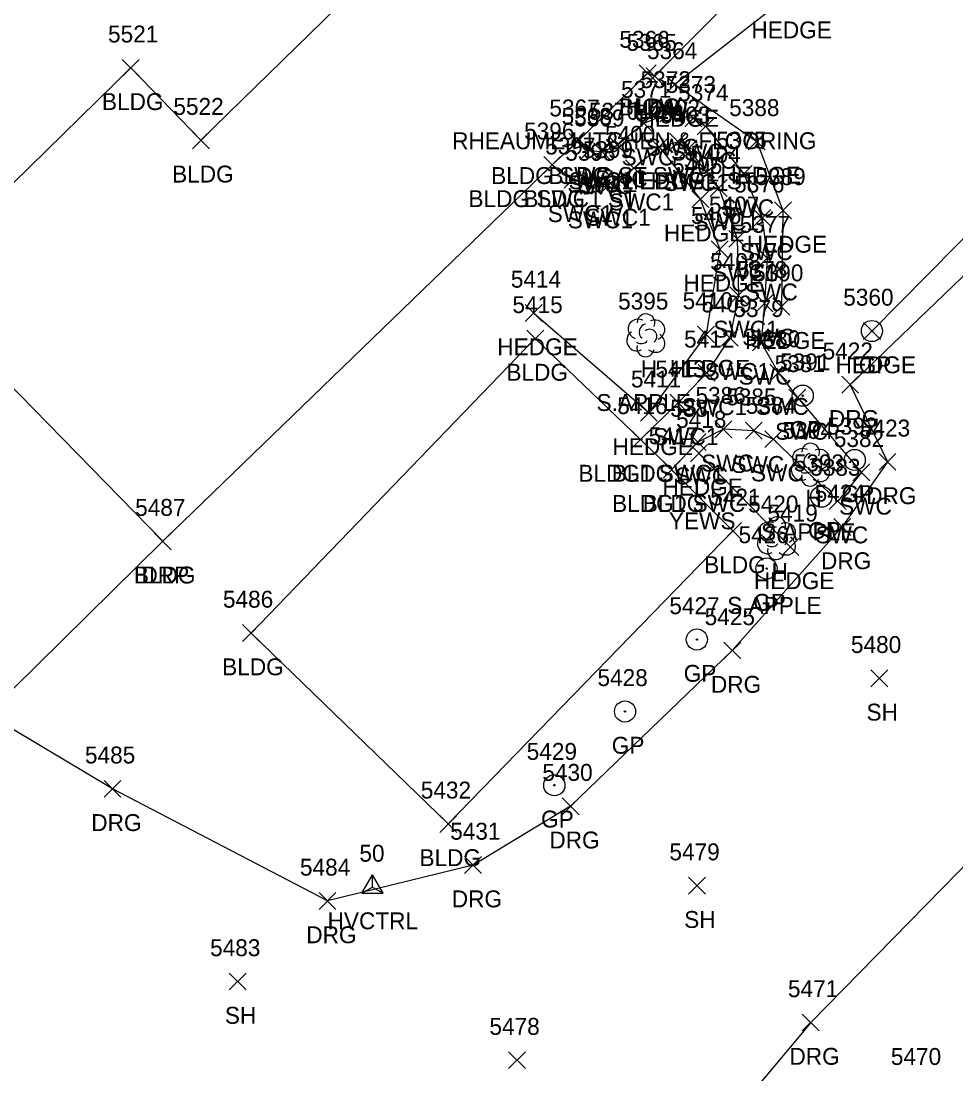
# Model space of a CAD drawing. Extents: x 1472233 to 1475777, y 540726 to 543442.
# Drawn here: x 1474616.2 to 1474726.8, y 541355.8 to 541480.4 of the extents above; entities that cross this region are included whole.
import ezdxf

# ---------------------------------------------------------------- set-up
doc = ezdxf.new("R2010")
doc.units = 0
for name, color, linetype in [('C_A', 7, 'Continuous'), ('C_I', 7, 'Continuous'), ('CPSM', 7, 'Continuous'), ('L_A', 7, 'Continuous'), ('L_C', 7, 'Continuous'), ('L_I', 7, 'Continuous'), ('L_TIC', 7, 'Continuous'), ('LAHR', 7, 'Continuous'), ('LBC', 7, 'Continuous'), ('LTD', 7, 'Continuous'), ('R_A', 7, 'Continuous'), ('R_I', 7, 'Continuous'), ('R_TIC', 7, 'Continuous'), ('RDG', 7, 'Continuous'), ('RDP', 7, 'Continuous'), ('RGP', 7, 'Continuous'), ('RSW', 7, 'Continuous')]:
    doc.layers.add(name, color=color, linetype=linetype)

msp = doc.modelspace()

# ---------------------------------------------------------------- linework, layer by layer
at = {"layer": 'CPSM'}
for p, q in [((1474656.5, 541377.23), (1474657.75, 541379.4)), ((1474659, 541377.23), (1474657.75, 541379.4)), ((1474657.75, 541377.95), (1474657.75, 541379.4)), ((1474656.5, 541377.23), (1474657.75, 541377.95)), ((1474657.75, 541377.95), (1474657.75, 541377.95)), ((1474657.75, 541377.95), (1474659, 541377.23)), ((1474656.5, 541377.23), (1474659, 541377.23))]:
    msp.add_line(p, q, dxfattribs=at)
at = {"layer": 'L_TIC'}
for points in [[(1474628.16, 541473.87), (1474630.16, 541475.87)], [(1474630.16, 541473.87), (1474628.16, 541475.87)], [(1474689.31, 541473.24), (1474691.31, 541475.24)], [(1474691.31, 541473.24), (1474689.31, 541475.24)], [(1474689.31, 541473.24), (1474691.31, 541475.24)], [(1474691.31, 541473.24), (1474689.31, 541475.24)], [(1474690.12, 541472.88), (1474692.12, 541474.88)], [(1474692.12, 541472.88), (1474690.12, 541474.88)], [(1474692.53, 541471.9), (1474694.53, 541473.9)], [(1474694.53, 541471.9), (1474692.53, 541473.9)], [(1474636.46, 541465.3), (1474638.46, 541467.3)], [(1474638.46, 541465.3), (1474636.46, 541467.3)], [(1474680.97, 541465.12), (1474682.97, 541467.12)], [(1474682.97, 541465.12), (1474680.97, 541467.12)], [(1474690.64, 541464.51), (1474692.64, 541466.51)], [(1474692.64, 541464.51), (1474690.64, 541466.51)], [(1474702.2, 541465.16), (1474704.2, 541467.16)], [(1474704.2, 541465.16), (1474702.2, 541467.16)], [(1474678, 541462.39), (1474680, 541464.39)], [(1474680, 541462.39), (1474678, 541464.39)], [(1474695.52, 541458.33), (1474697.52, 541460.33)], [(1474697.52, 541458.33), (1474695.52, 541460.33)], [(1474705.3, 541457), (1474707.3, 541459)], [(1474707.3, 541457), (1474705.3, 541459)], [(1474697.82, 541452.4), (1474699.82, 541454.4)], [(1474699.82, 541452.4), (1474697.82, 541454.4)], [(1474705.12, 541445.61), (1474707.12, 541447.61)], [(1474707.12, 541445.61), (1474705.12, 541447.61)], [(1474675.8, 541444.86), (1474677.8, 541446.86)], [(1474677.8, 541444.86), (1474675.8, 541446.86)], [(1474676, 541441.85), (1474678, 541443.85)], [(1474678, 541441.85), (1474676, 541443.85)], [(1474676, 541441.85), (1474678, 541443.85)], [(1474678, 541441.85), (1474676, 541443.85)], [(1474696.21, 541442.32), (1474698.21, 541444.32)], [(1474698.21, 541442.32), (1474696.21, 541444.32)], [(1474715.82, 541442.73), (1474717.82, 541444.73)], [(1474717.82, 541442.73), (1474715.82, 541444.73)], [(1474689.44, 541433.05), (1474691.44, 541435.05)], [(1474691.44, 541433.05), (1474689.44, 541435.05)], [(1474688.45, 541429.9), (1474690.45, 541431.9)], [(1474690.45, 541429.9), (1474688.45, 541431.9)], [(1474695.35, 541428.27), (1474697.35, 541430.27)], [(1474697.35, 541428.27), (1474695.35, 541430.27)], [(1474692.12, 541426.33), (1474694.12, 541428.33)], [(1474694.12, 541426.33), (1474692.12, 541428.33)], [(1474699.39, 541419.08), (1474701.39, 541421.08)], [(1474701.39, 541419.08), (1474699.39, 541421.08)], [(1474631.94, 541417.86), (1474633.94, 541419.86)], [(1474633.94, 541417.86), (1474631.94, 541419.86)], [(1474706.17, 541417.19), (1474708.17, 541419.19)], [(1474708.17, 541417.19), (1474706.17, 541419.19)], [(1474642.38, 541407), (1474644.38, 541409)], [(1474644.38, 541407), (1474642.38, 541409)], [(1474642.38, 541407), (1474644.38, 541409)], [(1474644.38, 541407), (1474642.38, 541409)], [(1474716.69, 541401.64), (1474718.69, 541403.64)], [(1474718.69, 541401.64), (1474716.69, 541403.64)], [(1474665.72, 541384.42), (1474667.72, 541386.42)], [(1474667.72, 541384.42), (1474665.72, 541386.42)], [(1474695.14, 541377.11), (1474697.14, 541379.11)], [(1474697.14, 541377.11), (1474695.14, 541379.11)], [(1474640.8, 541365.77), (1474642.8, 541367.77)], [(1474642.8, 541365.77), (1474640.8, 541367.77)], [(1474673.84, 541356.46), (1474675.84, 541358.46)], [(1474675.84, 541356.46), (1474673.84, 541358.46)]]:
    msp.add_lwpolyline(points, dxfattribs=at)
at = {"layer": 'LAHR'}
for points in [[(1474723.23, 541499.5), (1474706.87, 541483.35), (1474693.53, 541472.9), (1474703.2, 541466.16), (1474706.3, 541458), (1474706.12, 541446.61)], [(1474755.53, 541485.45), (1474742.31, 541469.68), (1474733.53, 541460.65), (1474716.82, 541443.73)], [(1474691.64, 541465.51), (1474696.52, 541459.33), (1474698.82, 541453.4), (1474697.21, 541443.32), (1474690.44, 541434.05), (1474676.8, 541445.86)], [(1474696.35, 541429.27), (1474707.17, 541418.19)]]:
    msp.add_lwpolyline(points, dxfattribs=at)
at = {"layer": 'LBC'}
for points in [[(1474667.61, 541497.68), (1474686.46, 541515.6), (1474709.41, 541493.59), (1474710.11, 541492.87), (1474691.12, 541473.88), (1474690.31, 541474.24)], [(1474690.31, 541474.24), (1474681.97, 541466.12), (1474679, 541463.39), (1474632.94, 541418.86), (1474609.18, 541443.15), (1474603.1, 541449.36), (1474629.16, 541474.87), (1474637.46, 541466.3), (1474668, 541496.15)], [(1474677, 541442.85), (1474689.45, 541430.9), (1474693.12, 541427.33), (1474700.39, 541420.08), (1474666.72, 541385.42), (1474643.38, 541408)], [(1474677, 541442.85), (1474643.38, 541408)]]:
    msp.add_lwpolyline(points, dxfattribs=at)
at = {"layer": 'LTD'}
for p, q in [((1474690.06, 541443.27), (1474690.06, 541443.27)), ((1474690.06, 541443.27), (1474690.06, 541443.27)), ((1474709.52, 541427.96), (1474709.52, 541427.96)), ((1474709.52, 541427.96), (1474709.52, 541427.96)), ((1474705.52, 541419.27), (1474705.52, 541419.27)), ((1474705.52, 541419.27), (1474705.52, 541419.27))]:
    msp.add_line(p, q, dxfattribs=at)
for centre in [(1474690.1, 541444.7), (1474709.57, 541429.4), (1474705.57, 541420.7)]:
    msp.add_arc(centre, 1.05, 335.5272, 180.9563, dxfattribs=at)
for centre, major_axis, ratio, start_param, end_param in [((1474689.27, 541443.93), (1.21, -0.51), 0.895232, 1.570796, 4.712389), ((1474691.1, 541443.85), (-1.14, -0.48), 0.949671, 1.570796, 4.712389), ((1474688.97, 541442.56), (0.58, -1.04), 0.959034, 3.141593, 6.283185), ((1474689.85, 541443.73), (-0.208, -0.792), 0.645439, 3.141593, 6.283185), ((1474690.56, 541443.1), (-0.5, 0.667), 0.989748, 3.141593, 6.283185), ((1474689.6, 541442.52), (-0.625, -0.083), 0.423636, 0, 3.141593), ((1474691.06, 541442.43), (-1.09, 0.79), 0.841452, 1.570796, 4.712389), ((1474690.06, 541441.77), (0.26, 1.06), 0.942809, 1.570796, 4.712389), ((1474708.73, 541428.63), (1.21, -0.51), 0.895232, 1.570796, 4.712389), ((1474710.57, 541428.55), (-1.14, -0.48), 0.949671, 1.570796, 4.712389), ((1474709.32, 541428.42), (-0.208, -0.792), 0.645439, 3.141593, 6.283185), ((1474710.02, 541427.8), (-0.5, 0.667), 0.989748, 3.141593, 6.283185), ((1474708.44, 541427.26), (0.58, -1.04), 0.959034, 3.141593, 6.283185), ((1474710.52, 541427.13), (-1.09, 0.79), 0.841452, 1.570796, 4.712389), ((1474709.52, 541426.46), (0.26, 1.06), 0.942809, 1.570796, 4.712389), ((1474709.07, 541427.21), (-0.625, -0.083), 0.423636, 0, 3.141593), ((1474704.73, 541419.94), (1.21, -0.51), 0.895232, 1.570796, 4.712389), ((1474706.56, 541419.85), (-1.14, -0.48), 0.949671, 1.570796, 4.712389), ((1474705.31, 541419.73), (-0.208, -0.792), 0.645439, 3.141593, 6.283185), ((1474706.02, 541419.1), (-0.5, 0.667), 0.989748, 3.141593, 6.283185), ((1474704.44, 541418.56), (0.58, -1.04), 0.959034, 3.141593, 6.283185), ((1474706.52, 541418.44), (-1.09, 0.79), 0.841452, 1.570796, 4.712389), ((1474705.52, 541417.77), (0.26, 1.06), 0.942809, 1.570796, 4.712389), ((1474705.06, 541418.52), (-0.625, -0.083), 0.423636, 0, 3.141593)]:
    msp.add_ellipse(centre, major_axis=major_axis, ratio=ratio, start_param=start_param, end_param=end_param, dxfattribs=at)
at = {"layer": 'R_TIC'}
for points in [[(1474691.72, 541468.47), (1474693.72, 541470.47)], [(1474693.72, 541468.47), (1474691.72, 541470.47)], [(1474694.69, 541467.9), (1474696.69, 541469.9)], [(1474696.69, 541467.9), (1474694.69, 541469.9)], [(1474688.84, 541467.32), (1474690.84, 541469.32)], [(1474690.84, 541467.32), (1474688.84, 541469.32)], [(1474696.17, 541466.93), (1474698.17, 541468.93)], [(1474698.17, 541466.93), (1474696.17, 541468.93)], [(1474680.97, 541465.12), (1474682.97, 541467.12)], [(1474682.97, 541465.12), (1474680.97, 541467.12)], [(1474682.43, 541464.13), (1474684.43, 541466.13)], [(1474684.43, 541464.13), (1474682.43, 541466.13)], [(1474685.69, 541464.73), (1474687.69, 541466.73)], [(1474687.69, 541464.73), (1474685.69, 541466.73)], [(1474690.64, 541464.51), (1474692.64, 541466.51)], [(1474692.64, 541464.51), (1474690.64, 541466.51)], [(1474692.87, 541465.12), (1474694.87, 541467.12)], [(1474694.87, 541465.12), (1474692.87, 541467.12)], [(1474694.1, 541464.3), (1474696.1, 541466.3)], [(1474696.1, 541464.3), (1474694.1, 541466.3)], [(1474683.92, 541463.94), (1474685.92, 541465.94)], [(1474685.92, 541463.94), (1474683.92, 541465.94)], [(1474678, 541462.39), (1474680, 541464.39)], [(1474680, 541462.39), (1474678, 541464.39)], [(1474687.68, 541462), (1474689.68, 541464)], [(1474689.68, 541462), (1474687.68, 541464)], [(1474680.44, 541460.62), (1474682.44, 541462.62)], [(1474682.44, 541460.62), (1474680.44, 541462.62)], [(1474700.67, 541461.31), (1474702.67, 541463.31)], [(1474702.67, 541461.31), (1474700.67, 541463.31)], [(1474682.81, 541459.88), (1474684.81, 541461.88)], [(1474684.81, 541459.88), (1474682.81, 541461.88)], [(1474684.89, 541460.19), (1474686.89, 541462.19)], [(1474686.89, 541460.19), (1474684.89, 541462.19)], [(1474697.7, 541459.64), (1474699.7, 541461.64)], [(1474699.7, 541459.64), (1474697.7, 541461.64)], [(1474702.85, 541456.12), (1474704.85, 541458.12)], [(1474704.85, 541456.12), (1474702.85, 541458.12)], [(1474699.88, 541453.64), (1474701.88, 541455.64)], [(1474701.88, 541453.64), (1474699.88, 541455.64)], [(1474703.44, 541451.35), (1474705.44, 541453.35)], [(1474705.44, 541451.35), (1474703.44, 541453.35)], [(1474700.03, 541446.95), (1474702.03, 541448.95)], [(1474702.03, 541446.95), (1474700.03, 541448.95)], [(1474703.12, 541446), (1474705.12, 541448)], [(1474705.12, 541446), (1474703.12, 541448)], [(1474699, 541441.94), (1474701, 541443.94)], [(1474701, 541441.94), (1474699, 541443.94)], [(1474702.71, 541441.39), (1474704.71, 541443.39)], [(1474704.71, 541441.39), (1474702.71, 541443.39)], [(1474696.29, 541437.78), (1474698.29, 541439.78)], [(1474698.29, 541437.78), (1474696.29, 541439.78)], [(1474704.74, 541437.81), (1474706.74, 541439.81)], [(1474706.74, 541437.81), (1474704.74, 541439.81)], [(1474713.25, 541436.37), (1474715.25, 541438.37)], [(1474715.25, 541436.37), (1474713.25, 541438.37)], [(1474692.9, 541434.24), (1474694.9, 541436.24)], [(1474694.9, 541434.24), (1474692.9, 541436.24)], [(1474707.01, 541434.87), (1474709.01, 541436.87)], [(1474709.01, 541434.87), (1474707.01, 541436.87)], [(1474698.26, 541431.11), (1474700.26, 541433.11)], [(1474700.26, 541431.11), (1474698.26, 541433.11)], [(1474701.85, 541430.94), (1474703.85, 541432.94)], [(1474703.85, 541430.94), (1474701.85, 541432.94)], [(1474688.45, 541429.9), (1474690.45, 541431.9)], [(1474690.45, 541429.9), (1474688.45, 541431.9)], [(1474695.22, 541429.59), (1474697.22, 541431.59)], [(1474697.22, 541429.59), (1474695.22, 541431.59)], [(1474704.16, 541429.94), (1474706.16, 541431.94)], [(1474706.16, 541429.94), (1474704.16, 541431.94)], [(1474717.66, 541427.25), (1474719.66, 541429.25)], [(1474719.66, 541427.25), (1474717.66, 541429.25)], [(1474692.12, 541426.33), (1474694.12, 541428.33)], [(1474694.12, 541426.33), (1474692.12, 541428.33)], [(1474714.58, 541426.01), (1474716.58, 541428.01)], [(1474716.58, 541426.01), (1474714.58, 541428.01)], [(1474711.78, 541422.61), (1474713.78, 541424.61)], [(1474713.78, 541422.61), (1474711.78, 541424.61)], [(1474712.31, 541419.55), (1474714.31, 541421.55)], [(1474714.31, 541419.55), (1474712.31, 541421.55)], [(1474631.94, 541417.86), (1474633.94, 541419.86)], [(1474633.94, 541417.86), (1474631.94, 541419.86)], [(1474699.3, 541404.93), (1474701.3, 541406.93)], [(1474701.3, 541404.93), (1474699.3, 541406.93)], [(1474626, 541388.57), (1474628, 541390.57)], [(1474628, 541388.57), (1474626, 541390.57)], [(1474680.18, 541386.51), (1474682.18, 541388.51)], [(1474682.18, 541386.51), (1474680.18, 541388.51)], [(1474668.64, 541379.55), (1474670.64, 541381.55)], [(1474670.64, 541379.55), (1474668.64, 541381.55)], [(1474651.43, 541375.3), (1474653.43, 541377.3)], [(1474653.43, 541375.3), (1474651.43, 541377.3)], [(1474708.58, 541360.92), (1474710.58, 541362.92)], [(1474710.58, 541360.92), (1474708.58, 541362.92)]]:
    msp.add_lwpolyline(points, dxfattribs=at)
at = {"layer": 'RDG'}
for points in [[(1474750.77, 541472.47), (1474714.25, 541437.37), (1474718.66, 541428.25), (1474713.31, 541420.55), (1474700.3, 541405.93), (1474681.18, 541387.51), (1474669.64, 541380.55), (1474652.43, 541376.3), (1474627, 541389.57), (1474612.18, 541398.39)], [(1474771.15, 541451.97), (1474774.94, 541432.6), (1474736.77, 541389.66), (1474709.58, 541361.92), (1474688.69, 541336.96), (1474660.55, 541324.88), (1474605.14, 541322.61), (1474559.08, 541319.27), (1474530.64, 541317.68), (1474505.35, 541356.73), (1474510.5, 541370.9), (1474529.64, 541392.89), (1474545.34, 541414.19), (1474568.38, 541444.04), (1474582.3, 541429.97)]]:
    msp.add_lwpolyline(points, dxfattribs=at)
at = {"layer": 'RDP'}
msp.add_lwpolyline([(1474632.94, 541418.86), (1474612.18, 541398.39), (1474590.26, 541420.46), (1474607.11, 541436.66), (1474606.73, 541439.08), (1474607.53, 541441.26), (1474609.18, 541443.15)], dxfattribs=at)
at = {"layer": 'RGP'}
for p, q in [((1474716.82, 541443.73), (1474716.82, 541443.73)), ((1474708.64, 541436.08), (1474708.64, 541436.08)), ((1474714.79, 541428.48), (1474714.79, 541428.48)), ((1474710.84, 541424.13), (1474710.84, 541424.13)), ((1474704.36, 541415.63), (1474704.36, 541415.63)), ((1474696.12, 541407.23), (1474696.12, 541407.23)), ((1474687.62, 541398.72), (1474687.62, 541398.72)), ((1474679.26, 541389.99), (1474679.26, 541389.99))]:
    msp.add_line(p, q, dxfattribs=at)
for centre, radius in [((1474716.82, 541443.73), 1.25), ((1474716.82, 541443.73), 0.0833), ((1474708.64, 541436.08), 1.25), ((1474708.64, 541436.08), 0.0833), ((1474714.79, 541428.48), 1.25), ((1474714.79, 541428.48), 0.0833), ((1474710.84, 541424.13), 1.25), ((1474710.84, 541424.13), 0.0833), ((1474704.36, 541415.63), 1.25), ((1474704.36, 541415.63), 0.0833), ((1474696.12, 541407.23), 1.25), ((1474696.12, 541407.23), 0.0833), ((1474687.62, 541398.72), 1.25), ((1474687.62, 541398.72), 0.0833), ((1474679.26, 541389.99), 1.25), ((1474679.26, 541389.99), 0.0833)]:
    msp.add_circle(centre, radius, dxfattribs=at)
at = {"layer": 'RSW'}
for points in [[(1474681.97, 541466.12), (1474683.43, 541465.13), (1474684.92, 541464.94), (1474686.69, 541465.73), (1474689.84, 541468.32), (1474692.72, 541469.47), (1474695.69, 541468.9), (1474697.17, 541467.93), (1474701.67, 541462.31), (1474703.85, 541457.12), (1474704.44, 541452.35), (1474704.12, 541447), (1474703.71, 541442.39), (1474705.74, 541438.81), (1474708.01, 541435.87), (1474715.58, 541427.01), (1474712.78, 541423.61), (1474705.16, 541430.94), (1474702.85, 541431.94), (1474699.26, 541432.11), (1474696.22, 541430.59), (1474693.12, 541427.33)], [(1474679, 541463.39), (1474681.44, 541461.62), (1474683.81, 541460.88), (1474685.89, 541461.19), (1474688.68, 541463), (1474691.64, 541465.51), (1474693.87, 541466.12), (1474695.1, 541465.3), (1474698.7, 541460.64), (1474700.88, 541454.64), (1474701.03, 541447.95), (1474700, 541442.94), (1474697.29, 541438.78), (1474693.9, 541435.24), (1474689.45, 541430.9)]]:
    msp.add_lwpolyline(points, dxfattribs=at)

# ---------------------------------------------------------------- texts
at = {"layer": 'C_A'}
msp.add_text('HVCTRL', height=2, dxfattribs=at).set_placement((1474652.44, 541372.95))
at = {"layer": 'C_I'}
msp.add_text('50', height=2, dxfattribs=at).set_placement((1474656.2, 541380.95))
at = {"layer": 'L_A'}
for s, p in [('HEDGE', (1474702.57, 541478.35)), ('BLDG', (1474625.75, 541469.87)), ('BLDG', (1474686.9, 541469.24)), ('HOW', (1474687.7, 541469.24)), ('HOW', (1474688.5, 541468.88)), ('HEDGE', (1474689.23, 541467.9)), ('BLDG', (1474634.05, 541461.3)), ('BLDG', (1474678.56, 541461.12)), ('HEDGE', (1474687.34, 541460.51)), ('HEDGE', (1474698.9, 541461.16)), ('BLDG', (1474675.59, 541458.39)), ('HEDGE', (1474692.22, 541454.33)), ('HEDGE', (1474702.01, 541453)), ('HEDGE', (1474694.52, 541448.4)), ('HEDGE', (1474701.82, 541441.61)), ('HEDGE', (1474672.51, 541440.86)), ('BLDG', (1474673.59, 541437.85)), ('BLDG', (1474673.59, 541437.85)), ('H', (1474689.49, 541438.27)), ('HEDGE', (1474692.91, 541438.32)), ('HEDGE', (1474712.52, 541438.73)), ('HEDGE', (1474686.14, 541429.05)), ('BLDG', (1474686.04, 541425.9)), ('HEDGE', (1474692.05, 541424.27)), ('H', (1474708.96, 541422.96)), ('BLDG', (1474689.71, 541422.33)), ('BLDG', (1474696.98, 541415.08)), ('H', (1474704.96, 541414.27)), ('BLDG', (1474629.53, 541413.86)), ('HEDGE', (1474702.87, 541413.19)), ('BLDG', (1474639.97, 541403)), ('BLDG', (1474639.97, 541403)), ('SH', (1474716.18, 541397.64)), ('BLDG', (1474663.31, 541380.42)), ('SH', (1474694.62, 541373.11)), ('SH', (1474640.29, 541361.77))]:
    msp.add_text(s, height=2, dxfattribs=at).set_placement(p)
at = {"layer": 'L_C'}
for s, p in [('RHEAUME KITCHEN & FLOORING', (1474667.17, 541465.24)), ('S.APPLE', (1474684.25, 541434.27)), ('YEWS', (1474692.81, 541420.27)), ('S.APPLE', (1474703.71, 541418.96)), ('S.APPLE', (1474699.71, 541410.27))]:
    msp.add_text(s, height=2, dxfattribs=at).set_placement(p)
at = {"layer": 'L_I'}
for s, p in [('5521', (1474626.47, 541477.87)), ('5366', (1474686.95, 541477.24)), ('5366', (1474686.95, 541477.24)), ('5365', (1474687.81, 541476.88)), ('5364', (1474690.22, 541475.9)), ('5522', (1474634.2, 541469.3)), ('5367', (1474678.67, 541469.12)), ('5388', (1474699.94, 541469.16)), ('5401', (1474688.87, 541468.51)), ('5396', (1474675.68, 541466.39)), ('5405', (1474693.18, 541462.33)), ('5389', (1474703.04, 541461)), ('5406', (1474695.43, 541456.4)), ('5390', (1474702.77, 541449.61)), ('5414', (1474674.11, 541448.86)), ('5360', (1474713.43, 541446.73)), ('5415', (1474674.3, 541445.85)), ('5415', (1474674.3, 541445.85)), ('5395', (1474686.8, 541446.27)), ('5410', (1474694.43, 541446.32)), ('5411', (1474688.32, 541437.05)), ('5416', (1474686.7, 541433.9)), ('5418', (1474693.66, 541432.27)), ('5394', (1474706.26, 541430.96)), ('5417', (1474690.42, 541430.33)), ('5421', (1474697.7, 541423.08)), ('5487', (1474629.68, 541421.86)), ('5420', (1474702.18, 541422.27)), ('5419', (1474704.47, 541421.19)), ('5486', (1474640.06, 541411)), ('5486', (1474640.06, 541411)), ('5480', (1474714.34, 541405.64)), ('5432', (1474663.46, 541388.42)), ('5479', (1474692.87, 541381.11)), ('5483', (1474638.54, 541369.77)), ('5478', (1474671.58, 541360.46)), ('5470', (1474719.06, 541356.9))]:
    msp.add_text(s, height=2, dxfattribs=at).set_placement(p)
at = {"layer": 'R_A'}
for s, p in [('SWC', (1474690.09, 541464.47)), ('SWC', (1474687.21, 541463.32)), ('SWC', (1474693.05, 541463.9)), ('SWC', (1474694.54, 541462.93)), ('BLDG SWC ST', (1474671.79, 541461.12)), ('SWC1 HEDGE ST', (1474680.94, 541460.51)), ('SWC', (1474684.05, 541460.73)), ('SWC1', (1474690.91, 541461.12)), ('SWC1', (1474692.14, 541460.3)), ('SWC', (1474680.79, 541460.13)), ('SWC', (1474682.28, 541459.94)), ('BLDG SWC1 ST', (1474669.1, 541458.39)), ('SWC1', (1474685.71, 541458)), ('SWC1', (1474678.48, 541456.62)), ('SWC', (1474699.03, 541457.31)), ('SWC1', (1474680.85, 541455.88)), ('SWC1', (1474682.93, 541456.19)), ('SWC1', (1474695.74, 541455.64)), ('SWC', (1474701.21, 541452.12)), ('SWC1', (1474697.92, 541449.64)), ('SWC', (1474701.81, 541447.35)), ('SWC1', (1474698.07, 541442.95)), ('SWC', (1474701.48, 541442)), ('SWC1', (1474697.04, 541437.94)), ('GP', (1474715.25, 541438.73)), ('SWC', (1474701.07, 541437.39)), ('SWC1', (1474694.33, 541433.78)), ('SWC', (1474703.1, 541433.81)), ('DRG', (1474711.74, 541432.37)), ('SWC', (1474705.37, 541430.87)), ('GP', (1474707.07, 541431.08)), ('SWC1', (1474690.94, 541430.24)), ('SWC', (1474696.62, 541427.11)), ('SWC', (1474700.21, 541426.94)), ('BLDG1 SWC1', (1474682.1, 541425.9)), ('SWC', (1474693.58, 541425.59)), ('SWC', (1474702.52, 541425.94)), ('GP', (1474713.22, 541423.48)), ('DRG', (1474716.15, 541423.25)), ('BLDG1 SWC', (1474686.09, 541422.33)), ('SWC', (1474712.94, 541422.01)), ('GP', (1474709.27, 541419.13)), ('SWC', (1474710.14, 541418.61)), ('DRG', (1474710.8, 541415.55)), ('DRP', (1474630.43, 541413.86)), ('GP', (1474702.79, 541410.63)), ('GP', (1474694.56, 541402.23)), ('DRG', (1474697.78, 541400.93)), ('GP', (1474686.05, 541393.72)), ('DRG', (1474624.49, 541384.57)), ('GP', (1474677.69, 541384.99)), ('DRG', (1474678.67, 541382.51)), ('DRG', (1474667.13, 541375.55)), ('DRG', (1474649.92, 541371.3)), ('DRG', (1474707.07, 541356.92))]:
    msp.add_text(s, height=2, dxfattribs=at).set_placement(p)
at = {"layer": 'R_I'}
for s, p in [('5372', (1474689.46, 541472.47)), ('5373', (1474692.43, 541471.9)), ('5371', (1474687.15, 541471.32)), ('5374', (1474693.91, 541470.93)), ('5367', (1474678.67, 541469.12)), ('5402', (1474690.53, 541469.12)), ('5368', (1474680.12, 541468.13)), ('5369', (1474681.61, 541467.94)), ('5370', (1474683.34, 541468.73)), ('5401', (1474688.87, 541468.51)), ('5403', (1474691.77, 541468.3)), ('5396', (1474675.68, 541466.39)), ('5400', (1474685.25, 541466)), ('5375', (1474698.41, 541465.31)), ('5397', (1474678.18, 541464.62)), ('5399', (1474682.62, 541464.19)), ('5398', (1474680.55, 541463.88)), ('5404', (1474695.36, 541463.64)), ('5376', (1474700.53, 541460.12)), ('5407', (1474697.55, 541457.64)), ('5377', (1474701.18, 541455.35)), ('5408', (1474697.69, 541450.95)), ('5378', (1474700.86, 541450)), ('5360', (1474713.43, 541446.73)), ('5409', (1474696.65, 541445.94)), ('5379', (1474700.44, 541445.39)), ('5412', (1474694.6, 541441.78)), ('5380', (1474702.39, 541441.81)), ('5422', (1474710.99, 541440.37)), ('5391', (1474705.95, 541439.08)), ('5413', (1474691.21, 541438.24)), ('5381', (1474705.32, 541438.87)), ('5386', (1474695.95, 541435.11)), ('5385', (1474699.59, 541434.94)), ('5416', (1474686.7, 541433.9)), ('5387', (1474692.96, 541433.59)), ('5384', (1474701.9, 541433.94)), ('5392', (1474711.53, 541431.48)), ('5423', (1474715.4, 541431.25)), ('5417', (1474690.42, 541430.33)), ('5382', (1474712.32, 541430.01)), ('5393', (1474707.58, 541427.13)), ('5383', (1474709.52, 541426.61)), ('5424', (1474710.05, 541423.55)), ('5487', (1474629.68, 541421.86)), ('5426', (1474701.05, 541418.63)), ('5427', (1474692.86, 541410.23)), ('5425', (1474697.04, 541408.93)), ('5428', (1474684.36, 541401.72)), ('5429', (1474675.99, 541392.99)), ('5485', (1474623.74, 541392.57)), ('5430', (1474677.84, 541390.51)), ('5431', (1474666.94, 541383.55)), ('5484', (1474649.17, 541379.3)), ('5471', (1474706.89, 541364.92))]:
    msp.add_text(s, height=2, dxfattribs=at).set_placement(p)

doc.saveas('drawing.dxf')
